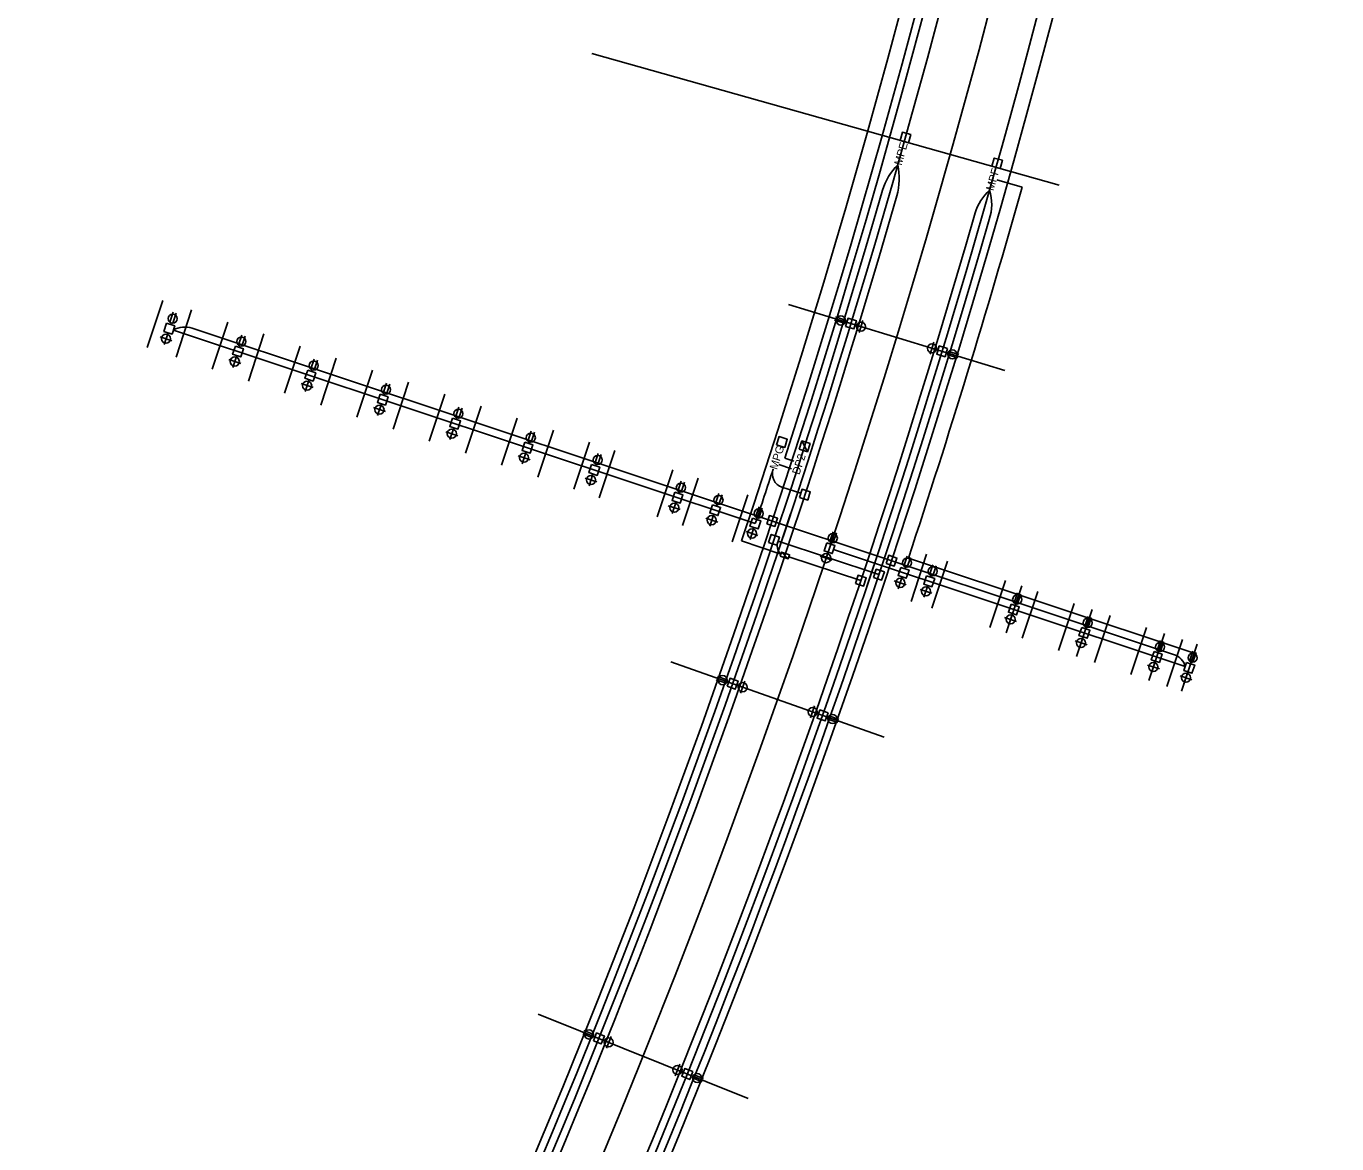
# Model space of a CAD drawing. Extents: x 927572 to 929124, y 636573 to 637910.
# Drawn here: x 928945.2 to 929117.2, y 637493.5 to 637640 of the extents above; entities that cross this region are included whole.
import ezdxf

# ---------------------------------------------------------------- set-up
doc = ezdxf.new("R2010")
doc.units = 0
for name, color, linetype in [('ConduitOT', 7, 'Continuous'), ('Miscellaneous4', 7, 'Continuous'), ('Miscellaneous7', 7, 'Continuous'), ('ScratchEle_dp', 7, 'Continuous')]:
    doc.layers.add(name, color=color, linetype=linetype)

msp = doc.modelspace()

# ---------------------------------------------------------------- linework, layer by layer
at = {"layer": 'ConduitOT'}
for p, q in [((929072.54, 637619.88), (929075.88, 637618.93)), ((929040.87, 637574.81), (928964.54, 637600.19)), ((929095.85, 637557.59), (928966.99, 637600.43)), ((929043.97, 637582.55), (929045.61, 637582)), ((929045.93, 637582.97), (929044.73, 637583.36)), ((929046.85, 637578.77), (929044.37, 637579.58)), ((929044.21, 637570.81), (929039.06, 637572.53)), ((929057.08, 637568.11), (929043.86, 637572.51)), ((929054.71, 637567.32), (929045.28, 637570.45)), ((929097.27, 637556.07), (929051.14, 637571.4)), ((929098.43, 637557.79), (929060.96, 637570.25)), ((929097.98, 637556.42), (929098.43, 637557.79))]:
    msp.add_line(p, q, dxfattribs=at)
for centre, radius, start, end in [((927949.43, 637937.64), 1152.17, 317.11857, 357.69675), ((927949.43, 637937.64), 1149.17, 341.47525, 357.69675), ((927949.43, 637937.64), 1151.17, 342.07611, 357.69675), ((927949.43, 637937.64), 1168.67, 317.11857, 357.69675), ((927949.43, 637937.64), 1154.17, 330.72814, 357.69675), ((927949.43, 637937.64), 1166.67, 330.72785, 357.69675), ((929064.67, 637616.52), 7.38, 133.8018, 164.0363), ((929051.53, 637620.07), 8.22, 343.9257, 12.5213), ((927949.43, 637937.64), 1153.17, 317.11857, 343.93655), ((927949.43, 637937.64), 1170.67, 341.70972, 344.20219), ((929075.73, 637613.83), 6.24, 131.3124, 164.0797), ((929065.75, 637616.7), 6.14, 340.7946, 17.3304), ((927949.43, 637937.64), 1155.17, 317.11857, 343.92577), ((927949.43, 637937.64), 1165.67, 317.11857, 343.95974), ((927949.43, 637937.64), 1167.67, 317.11857, 343.94334), ((928966.04, 637597.55), 3.03, 71.6118, 119.5211), ((927949.43, 637937.64), 1150.17, 341.61184, 341.98643), ((929044.94, 637581.32), 1.83, 159.6665, 251.8915), ((929045.26, 637571.91), 1.52, 157.1038, 226.5463), ((929095.17, 637555.54), 2.17, 14.179, 71.6118)]:
    msp.add_arc(centre, radius, start, end, dxfattribs=at)
at = {"layer": 'Miscellaneous4'}
for p, q in [((928964.49, 637602.53), (928964.06, 637601.23)), ((928964.19, 637600.9), (928964.26, 637601.11)), ((928964.92, 637602.39), (928964.48, 637601.08)), ((929051.25, 637601.47), (929052.57, 637601.07)), ((929051.38, 637601.9), (929052.7, 637601.5)), ((929052.89, 637601.2), (929052.67, 637601.27)), ((929053.96, 637600.88), (929055.54, 637600.4)), ((929054.51, 637599.85), (929054.99, 637601.42)), ((928962.79, 637599.31), (928964.35, 637598.79)), ((928963.83, 637599.83), (928963.31, 637598.27)), ((928973.51, 637599.53), (928973.07, 637598.23)), ((928973.93, 637599.39), (928973.5, 637598.09)), ((928973.2, 637597.9), (928973.27, 637598.12)), ((929064.84, 637597.56), (929063.27, 637598.04)), ((929064.3, 637598.58), (929063.82, 637597.01)), ((929067.56, 637596.97), (929066.24, 637597.37)), ((928971.81, 637596.32), (928973.37, 637595.8)), ((928972.85, 637596.84), (928972.33, 637595.28)), ((928983, 637596.38), (928982.56, 637595.08)), ((928983.42, 637596.24), (928982.99, 637594.93)), ((929065.92, 637597.23), (929066.14, 637597.17)), ((929067.43, 637596.54), (929066.11, 637596.94)), ((928982.69, 637594.75), (928982.76, 637594.96)), ((928981.3, 637593.16), (928982.86, 637592.64)), ((928982.34, 637593.68), (928981.82, 637592.12)), ((928992.48, 637593.22), (928992.05, 637591.92)), ((928992.91, 637593.08), (928992.48, 637591.78)), ((928991.82, 637590.53), (928991.31, 637588.97)), ((928992.18, 637591.59), (928992.25, 637591.81)), ((928990.79, 637590.01), (928992.35, 637589.49)), ((929001.97, 637590.07), (929001.54, 637588.77)), ((929002.4, 637589.93), (929001.97, 637588.62)), ((929001.31, 637587.37), (929000.8, 637585.81)), ((929001.67, 637588.44), (929001.74, 637588.65)), ((929000.28, 637586.85), (929001.83, 637586.33)), ((929011.46, 637586.92), (929011.03, 637585.61)), ((929011.16, 637585.29), (929011.23, 637585.5)), ((929011.89, 637586.77), (929011.46, 637585.47)), ((929009.76, 637583.7), (929011.32, 637583.18)), ((929010.8, 637584.22), (929010.29, 637582.66)), ((929020.24, 637584), (929019.81, 637582.69)), ((929020.67, 637583.86), (929020.23, 637582.55)), ((929019.94, 637582.37), (929020.01, 637582.58)), ((929018.54, 637580.78), (929020.1, 637580.26)), ((929019.58, 637581.3), (929019.06, 637579.74)), ((929031.15, 637580.37), (929030.72, 637579.07)), ((929031.58, 637580.23), (929031.15, 637578.92)), ((929030.85, 637578.74), (929030.92, 637578.95)), ((929036.08, 637578.73), (929035.65, 637577.43)), ((929036.51, 637578.59), (929036.08, 637577.29)), ((929029.46, 637577.15), (929031.01, 637576.63)), ((929030.49, 637577.67), (929029.98, 637576.11)), ((929035.78, 637577.1), (929035.85, 637577.31)), ((929041.36, 637576.98), (929040.92, 637575.67)), ((929041.78, 637576.84), (929041.35, 637575.53)), ((929034.39, 637575.51), (929035.94, 637574.99)), ((929035.42, 637576.03), (929034.91, 637574.47)), ((929041.05, 637575.35), (929041.12, 637575.56)), ((929039.66, 637573.76), (929041.22, 637573.24)), ((929040.7, 637574.28), (929040.18, 637572.72)), ((929051.09, 637573.74), (929050.65, 637572.44)), ((929051.51, 637573.6), (929051.08, 637572.3)), ((929050.78, 637572.11), (929050.85, 637572.33)), ((929049.39, 637570.53), (929050.95, 637570.01)), ((929050.43, 637571.05), (929049.91, 637569.49)), ((929060.81, 637570.51), (929060.37, 637569.21)), ((929061.24, 637570.37), (929060.8, 637569.07)), ((929060.5, 637568.88), (929060.57, 637569.1)), ((929064.18, 637569.39), (929063.74, 637568.09)), ((929064.6, 637569.25), (929064.17, 637567.95)), ((929059.11, 637567.29), (929060.67, 637566.78)), ((929060.15, 637567.81), (929059.63, 637566.25)), ((929063.52, 637566.69), (929063, 637565.14)), ((929063.87, 637567.76), (929063.94, 637567.98)), ((929062.48, 637566.17), (929064.04, 637565.66)), ((929075.27, 637565.7), (929074.84, 637564.4)), ((929075.7, 637565.56), (929075.27, 637564.26)), ((929074.61, 637563.01), (929074.1, 637561.45)), ((929074.97, 637564.07), (929075.04, 637564.29)), ((929073.58, 637562.48), (929075.14, 637561.97)), ((929084.53, 637562.63), (929084.09, 637561.32)), ((929084.22, 637561), (929084.29, 637561.21)), ((929084.95, 637562.49), (929084.52, 637561.18)), ((929083.87, 637559.93), (929083.35, 637558.37)), ((929082.83, 637559.41), (929084.39, 637558.89)), ((929094.02, 637559.47), (929093.58, 637558.17)), ((929093.71, 637557.84), (929093.78, 637558.06)), ((929094.44, 637559.33), (929094.01, 637558.03)), ((929098.29, 637558.05), (929097.85, 637556.75)), ((929098.71, 637557.91), (929098.28, 637556.61)), ((929092.32, 637556.25), (929093.88, 637555.74)), ((929093.36, 637556.78), (929092.84, 637555.22)), ((929097.98, 637556.42), (929098.05, 637556.64)), ((929035.75, 637554.32), (929037.04, 637553.86)), ((929035.9, 637554.74), (929037.19, 637554.29)), ((929096.59, 637554.84), (929098.15, 637554.32)), ((929097.63, 637555.36), (929097.11, 637553.8)), ((929037.37, 637553.99), (929037.16, 637554.06)), ((929038.43, 637553.61), (929039.98, 637553.07)), ((929038.93, 637552.56), (929039.48, 637554.11)), ((929049.16, 637549.83), (929047.61, 637550.38)), ((929048.66, 637550.88), (929048.11, 637549.33)), ((929050.22, 637549.45), (929050.43, 637549.38)), ((929051.85, 637549.12), (929050.55, 637549.58)), ((929051.7, 637548.7), (929050.4, 637549.15)), ((929018.4, 637508.3), (929019.67, 637507.79)), ((929018.23, 637507.88), (929019.5, 637507.37)), ((929019.84, 637507.48), (929019.63, 637507.56)), ((929020.88, 637507.06), (929022.41, 637506.45)), ((929021.34, 637505.99), (929021.95, 637507.52)), ((929031.44, 637502.82), (929029.91, 637503.43)), ((929030.98, 637503.89), (929030.37, 637502.36)), ((929032.48, 637502.4), (929032.69, 637502.32)), ((929033.92, 637501.58), (929032.65, 637502.09)), ((929034.09, 637502), (929032.81, 637502.51))]:
    msp.add_line(p, q, dxfattribs=at)
for centre in [(928964.45, 637601.68), (929052.1, 637601.44), (929054.75, 637600.64), (928963.57, 637599.05), (928973.46, 637598.68), (929064.06, 637597.8), (929066.71, 637596.99), (928972.59, 637596.06), (928982.95, 637595.53), (928982.08, 637592.9), (928992.44, 637592.37), (928991.57, 637589.75), (929001.93, 637589.22), (929001.06, 637586.59), (929011.42, 637586.07), (929010.54, 637583.44), (929020.2, 637583.15), (929019.32, 637580.52), (929031.11, 637579.52), (929036.04, 637577.88), (929030.24, 637576.89), (929041.31, 637576.13), (929035.16, 637575.25), (929040.44, 637573.5), (929051.04, 637572.89), (929050.17, 637570.27), (929060.76, 637569.66), (929064.13, 637568.54), (929059.89, 637567.03), (929063.26, 637565.91), (929075.23, 637564.85), (929074.36, 637562.23), (929084.48, 637561.78), (929083.61, 637559.15), (929093.97, 637558.62), (929098.24, 637557.2), (929093.1, 637556), (929036.6, 637554.26), (929097.37, 637554.58), (929039.21, 637553.34), (929048.39, 637550.1), (929051, 637549.18), (929019.07, 637507.79), (929021.64, 637506.75), (929030.67, 637503.13), (929033.24, 637502.09)]:
    msp.add_circle(centre, 0.597, dxfattribs=at)
at = {"layer": 'Miscellaneous7'}
for p, q in [((929047.7, 637584.23), (929046.98, 637585.65)), ((929046.98, 637585.65), (929047.7, 637584.23)), ((929045.19, 637570.18), (929044.3, 637571.07))]:
    msp.add_line(p, q, dxfattribs=at)
for points in [[(929059.88, 637625.05), (929060.18, 637626.14), (929061.27, 637625.83), (929060.96, 637624.75)], [(929071.91, 637621.67), (929072.22, 637622.75), (929073.3, 637622.45), (929073, 637621.36)], [(928963.65, 637601.08), (928964.72, 637600.72), (928964.36, 637599.66), (928963.3, 637600.01)], [(929052.72, 637600.67), (929053.05, 637601.74), (929054.13, 637601.41), (929053.8, 637600.34)], [(928972.67, 637598.08), (928973.73, 637597.73), (928973.38, 637596.66), (928972.31, 637597.01)], [(929066.09, 637597.77), (929065.76, 637596.69), (929064.68, 637597.02), (929065.01, 637598.1)], [(928982.16, 637594.93), (928983.22, 637594.57), (928982.87, 637593.5), (928981.8, 637593.86)], [(928991.65, 637591.77), (928992.71, 637591.42), (928992.36, 637590.35), (928991.29, 637590.7)], [(929001.14, 637588.62), (929002.2, 637588.26), (929001.85, 637587.19), (929000.78, 637587.55)], [(929010.62, 637585.46), (929011.69, 637585.11), (929011.34, 637584.04), (929010.27, 637584.4)], [(929043.66, 637585.14), (929044, 637586.22), (929045.07, 637585.87), (929044.73, 637584.8)], [(929046.63, 637584.58), (929046.98, 637585.65), (929048.05, 637585.3), (929047.7, 637584.23)], [(929019.4, 637582.54), (929020.47, 637582.19), (929020.12, 637581.12), (929019.05, 637581.48)], [(929030.32, 637578.92), (929031.38, 637578.56), (929031.03, 637577.49), (929029.96, 637577.85)], [(929046.68, 637578.23), (929047.02, 637579.3), (929048.09, 637578.96), (929047.75, 637577.89)], [(929035.25, 637577.28), (929036.31, 637576.92), (929035.96, 637575.86), (929034.89, 637576.21)], [(929040.52, 637575.53), (929041.58, 637575.17), (929041.23, 637574.1), (929040.16, 637574.46)], [(929042.37, 637574.78), (929042.73, 637575.84), (929043.8, 637575.49), (929043.44, 637574.42)], [(929042.61, 637572.33), (929042.97, 637573.39), (929044.04, 637573.04), (929043.68, 637571.97)], [(929050.25, 637572.29), (929051.32, 637571.94), (929050.96, 637570.87), (929049.89, 637571.22)], [(929044.13, 637570.54), (929044.3, 637571.07), (929045.37, 637570.72), (929045.19, 637570.18)], [(929058.03, 637569.57), (929058.39, 637570.64), (929059.46, 637570.28), (929059.1, 637569.22)], [(929056.37, 637567.75), (929056.73, 637568.82), (929057.8, 637568.46), (929057.44, 637567.4)], [(929059.97, 637569.06), (929061.04, 637568.7), (929060.68, 637567.64), (929059.61, 637567.99)], [(929054, 637566.96), (929054.36, 637568.03), (929055.42, 637567.67), (929055.07, 637566.6)], [(929063.34, 637567.94), (929064.41, 637567.58), (929064.05, 637566.52), (929062.98, 637566.87)], [(929074.44, 637564.25), (929075.5, 637563.9), (929075.15, 637562.83), (929074.08, 637563.18)], [(929083.69, 637561.17), (929084.76, 637560.82), (929084.4, 637559.75), (929083.33, 637560.11)], [(929093.18, 637558.02), (929094.24, 637557.67), (929093.89, 637556.6), (929092.82, 637556.95)], [(929097.45, 637556.6), (929098.52, 637556.25), (929098.16, 637555.18), (929097.09, 637555.53)], [(929037.19, 637553.46), (929037.56, 637554.52), (929038.62, 637554.14), (929038.25, 637553.08)], [(929050.41, 637549.99), (929050.03, 637548.92), (929048.97, 637549.3), (929049.35, 637550.36)], [(929019.63, 637506.96), (929020.05, 637508), (929021.09, 637507.58), (929020.67, 637506.54)], [(929032.69, 637502.92), (929032.27, 637501.88), (929031.23, 637502.3), (929031.65, 637503.34)]]:
    msp.add_lwpolyline(points, close=True, dxfattribs=at)
msp.add_lwpolyline([(929047.7, 637584.23), (929048.05, 637585.3), (929046.98, 637585.65)], dxfattribs=at)
at = {"layer": 'ScratchEle_dp'}
for p, q in [((929080.72, 637619.19), (929019.41, 637636.44)), ((928961.09, 637597.91), (928963.14, 637604.08)), ((928966.93, 637602.82), (928964.88, 637596.65)), ((929073.59, 637594.89), (929045.22, 637603.54)), ((928971.68, 637601.24), (928969.63, 637595.07)), ((928976.42, 637599.67), (928974.37, 637593.5)), ((928981.17, 637598.09), (928979.12, 637591.92)), ((928985.91, 637596.51), (928983.86, 637590.34)), ((928990.66, 637594.93), (928988.6, 637588.77)), ((928995.4, 637593.36), (928993.35, 637587.19)), ((929000.14, 637591.78), (928998.09, 637585.61)), ((929004.89, 637590.2), (929002.84, 637584.03)), ((929009.63, 637588.62), (929007.58, 637582.46)), ((929014.38, 637587.05), (929012.33, 637580.88)), ((929019.12, 637585.47), (929017.07, 637579.3)), ((929022.44, 637584.37), (929020.39, 637578.2)), ((929030.04, 637581.84), (929027.99, 637575.67)), ((929033.36, 637580.74), (929031.31, 637574.57)), ((929039.9, 637578.56), (929037.85, 637572.4)), ((929045.51, 637576.1), (929043.64, 637570.47)), ((929057.37, 637572.16), (929055.5, 637566.53)), ((929063.35, 637570.77), (929061.3, 637564.6)), ((929066.09, 637569.86), (929064.04, 637563.69)), ((929073.68, 637567.33), (929071.63, 637561.16)), ((929075.82, 637566.62), (929073.77, 637560.46)), ((929077.95, 637565.91), (929075.9, 637559.75)), ((929082.7, 637564.34), (929080.65, 637558.17)), ((929085.07, 637563.55), (929083.02, 637557.38)), ((929087.44, 637562.76), (929085.39, 637556.59)), ((929092.19, 637561.18), (929090.14, 637555.01)), ((929094.56, 637560.39), (929092.51, 637554.22)), ((929096.93, 637559.6), (929094.88, 637553.44)), ((929098.83, 637558.97), (929096.78, 637552.81)), ((929057.79, 637546.79), (929029.81, 637556.65)), ((929039.92, 637499.41), (929012.39, 637510.47))]:
    msp.add_line(p, q, dxfattribs=at)
msp.add_arc((927949.43, 637937.64), 1160.42, 317.11857, 357.69675, dxfattribs=at)

# ---------------------------------------------------------------- texts
at = {"layer": 'Miscellaneous4'}
for s, rotation, p in [('MPE', 74.2917, (929060.07, 637621.71)), ('MPF', 74.2707, (929072.12, 637618.38)), ('MPG', 72.1888, (929043.72, 637581.8))]:
    msp.add_text(s, height=1.05, rotation=rotation, dxfattribs=at).set_placement(p)
at = {"layer": 'Miscellaneous7'}
msp.add_text('DP2', height=1.05, rotation=72.0582, dxfattribs=at).set_placement((929046.66, 637581.13))

doc.saveas('drawing.dxf')
